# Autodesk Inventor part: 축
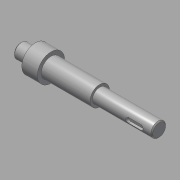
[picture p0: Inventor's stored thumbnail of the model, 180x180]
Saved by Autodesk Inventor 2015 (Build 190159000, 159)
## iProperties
Created: 2015-09
Part Number: 축
Material: 강철, 연강
Document SubType Name: Modeling
Designer: mduedu
Density: 7.86 g/cm^3
Mass: 263.424 g
Surface Area: 86.4309 cm^2
Volume: 33.5145 cm^3
Appearance: 강철
Author: mduedu
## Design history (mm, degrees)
sketch "스케치1"
  geometry: L1 (-71, 0)-(71, 0); L2 (-71, 0)-(-71, 7.5); L3 (-71, 7.5)-(-56, 7.5); L4 (-56, 7.5)-(-56, 14); L5 (-56, 14)-(-40, 14); L6 (-40, 14)-(-40, 10); L7 (-40, 10)-(10, 10); L8 (10, 10)-(10, 7.5); L9 (10, 7.5)-(71, 7.5); L10 (71, 7.5)-(71, 0); 2 further points
  constraints: 20 end point, 5 parallel, 2 horizontal, 2 perpendicular, 1 coincident, 1 midpoint, 1 vertical
  dimensions: "d0" = 142 distance of L1.start L1.end; "d2" = 16 distance of L4.end L5.end; "d3" = 50 distance of L6.end L7.end; "d5" = 15 diameter of L3 L1; "d6" = 15 diameter of L9 L1; "d7" = 20 diameter of L7 L1; "d8" = 28 diameter of L5 L1; "d31" = 15 distance of L2.end L3.end
revolve "회전1" sketch "스케치1" stored, may be unused: angle "d9" = 90 deg
node "작업 평면1"
sketch "스케치2"
  geometry: L1 (6, 2.5)-(19, 2.5); L2 (19, -2.5)-(6, -2.5); L3 (6, 2.5)-(19, -2.5); L4 (19, 2.5)-(6, -2.5); L5 (30.5, -7.5)-(30.5, 7.5) reference; A1 r 2.5 centre (6, 0) between (6, 2.5) and (6, -2.5); A2 r 2.5 centre (19, 0) between (19, -2.5) and (19, 2.5); 2 further points
  constraints: 8 end point, 4 point on circle, 4 tangent, 2 centre point, 2 midpoint, 1 horizontal, 1 horizontal alignment, 1 parallel
  dimensions: "d10" = 18 dimension on A2 A1; "d12" = 9 distance edge to line of A2 L5; "d13" = 5 distance between parallel lines of L2 L1
extrude "돌출1" cut sketch "스케치2" distance "d14" = 3; taper "d15" = 0 deg
node "작업 평면2"
sketch "스케치4"
  geometry: L1 (3, -3)-(-13, -3); L2 (-13, 3)-(3, 3); L3 (-25, 10)-(-25, -10) reference; A1 r 3 centre (-13, 0) between (-13, 3) and (-13, -3); A2 r 3 centre (3, 0) between (3, -3) and (3, 3); 1 further point
  constraints: 4 end point, 4 point on circle, 4 tangent, 2 centre point, 1 horizontal, 1 horizontal alignment, 1 parallel
  dimensions: "d16" = 22 dimension on A1 A2; "d18" = 6 distance between parallel lines of L2 L1; "d19" = 9 distance edge to line of A1 L3
extrude "돌출2" cut sketch "스케치4" distance "d20" = 3.5; taper "d21" = 0 deg
sketch "스케치5"
  geometry: L1 (10, 7.5)-(71, 7.5) reference; L2 (10, -7.5)-(71, -7.5) reference; L3 (45, 7.5)-(45, -7.5); L4 (45, -5.5)-(43, -7.5); L5 (45, -7.5)-(43, -7.5); L6 (45, -7.5)-(45, -5.5); L7 (10, -10)-(10, 10) reference; 1 further point
  constraints: 8 end point, 4 point on line, 1 collinear, 1 perpendicular
  dimensions: "d22" = 4 diameter of L4.end L3; "d24" = 45 deg angle of L3 L4; "d26" = 35 distance between parallel lines of L3 L7
revolve "회전2" sketch "스케치5" stored, may be unused: angle "d27" = 90 deg
chamfer "모따기1" distance "d28" = 1; stored, may be unused: second distance "d29" = 2, angle "d30" = 45 deg
sketch "스케치6"
  geometry: L1 (45, -5.5)-(43, -7.5) reference; L2 (45, -5.5)-(47, -7.5) reference; 2 further points
  constraints: 1 coincident
node "솔리드1"
